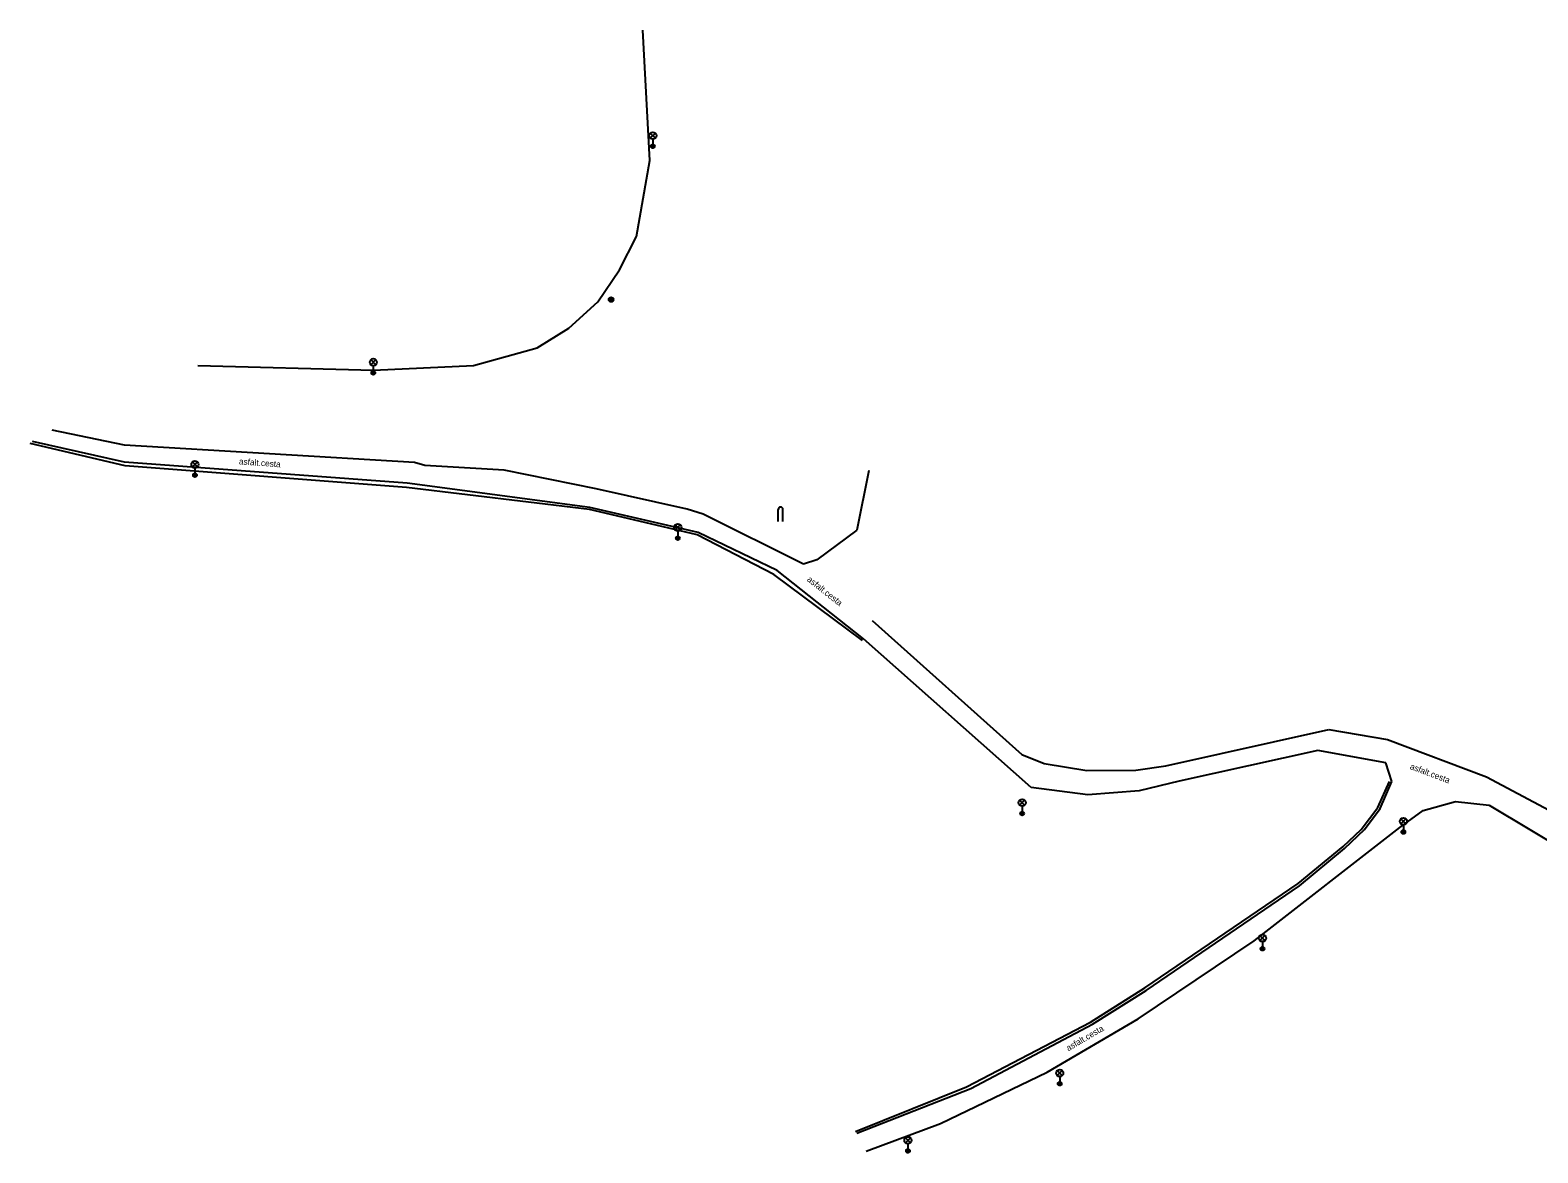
# Model space of a CAD drawing. Extents: x -639371 to -639058, y -1138650 to -1138362.
# Drawn here: x -639371.1 to -639212.8, y -1138642.6 to -1138524.7 of the extents above; entities that cross this region are included whole.
import ezdxf

# ---------------------------------------------------------------- set-up
doc = ezdxf.new("R2010")
doc.units = 0
for name, color, linetype in [('Vrstva 11', 7, 'Continuous'), ('Vrstva 25', 7, 'Continuous'), ('Vrstva 33', 7, 'Continuous'), ('Vrstva 38', 7, 'Continuous'), ('Vrstva 40', 7, 'Continuous'), ('Vrstva 9', 7, 'Continuous')]:
    doc.layers.add(name, color=color, linetype=linetype)

msp = doc.modelspace()

# ---------------------------------------------------------------- linework, layer by layer
at = {"layer": 'Vrstva 11'}
for p, q in [((-639361.16, -1138568.24), (-639368.75, -1138566.66)), ((-639361.16, -1138570.04), (-639370.81, -1138567.86)), ((-639330.69, -1138570.07), (-639361.16, -1138568.24)), ((-639331.46, -1138572.23), (-639361.16, -1138570.04)), ((-639329.62, -1138570.37), (-639330.69, -1138570.07)), ((-639321.27, -1138570.85), (-639329.62, -1138570.37)), ((-639311.61, -1138572.82), (-639321.27, -1138570.85)), ((-639283, -1138570.89), (-639284.26, -1138577.18)), ((-639312.29, -1138574.79), (-639331.46, -1138572.23)), ((-639302.07, -1138574.96), (-639311.61, -1138572.82)), ((-639300.92, -1138577.4), (-639312.29, -1138574.79)), ((-639300.38, -1138575.5), (-639302.07, -1138574.96)), ((-639289.86, -1138580.73), (-639300.38, -1138575.5)), ((-639292.61, -1138581.41), (-639300.92, -1138577.4)), ((-639284.26, -1138577.18), (-639288.44, -1138580.29)), ((-639283.55, -1138588.58), (-639292.61, -1138581.41)), ((-639288.44, -1138580.29), (-639289.86, -1138580.73)), ((-639282.64, -1138586.64), (-639266.93, -1138600.74)), ((-639265.95, -1138604.18), (-639283.55, -1138588.58)), ((-639251.8, -1138601.92), (-639234.71, -1138598.09)), ((-639234.71, -1138598.09), (-639228.53, -1138599.15)), ((-639235.85, -1138600.3), (-639250.41, -1138603.54)), ((-639228.72, -1138601.59), (-639235.85, -1138600.3)), ((-639228.53, -1138599.15), (-639218.13, -1138603.06)), ((-639266.93, -1138600.74), (-639264.57, -1138601.67)), ((-639264.57, -1138601.67), (-639260.09, -1138602.42)), ((-639254.95, -1138602.39), (-639251.8, -1138601.92)), ((-639228.08, -1138603.56), (-639228.72, -1138601.59)), ((-639260.09, -1138602.42), (-639254.95, -1138602.39)), ((-639250.41, -1138603.54), (-639254.61, -1138604.56)), ((-639229.32, -1138606.4), (-639228.08, -1138603.56)), ((-639218.13, -1138603.06), (-639209.92, -1138607.44)), ((-639259.99, -1138604.98), (-639265.95, -1138604.18)), ((-639254.61, -1138604.56), (-639259.99, -1138604.98)), ((-639230.97, -1138608.59), (-639229.32, -1138606.4)), ((-639227.26, -1138608.39), (-639224.79, -1138606.61)), ((-639224.79, -1138606.61), (-639221.39, -1138605.67)), ((-639221.39, -1138605.67), (-639217.88, -1138606.06)), ((-639217.88, -1138606.06), (-639207.21, -1138612.43)), ((-639242.53, -1138620.3), (-639227.26, -1138608.39)), ((-639233.07, -1138610.6), (-639230.97, -1138608.59)), ((-639237.77, -1138614.51), (-639233.07, -1138610.6)), ((-639253.88, -1138625.5), (-639237.77, -1138614.51)), ((-639254.71, -1138628.49), (-639242.53, -1138620.3)), ((-639259.52, -1138629.07), (-639253.88, -1138625.5)), ((-639272.3, -1138635.8), (-639259.52, -1138629.07)), ((-639264.28, -1138634.11), (-639254.71, -1138628.49)), ((-639275.46, -1138639.47), (-639264.28, -1138634.11)), ((-639284.25, -1138640.49), (-639272.3, -1138635.8)), ((-639283.29, -1138642.38), (-639275.46, -1138639.47))]:
    msp.add_line(p, q, dxfattribs=at)
at = {"layer": 'Vrstva 25'}
for radius in [0.25, 0.2, 0.15, 0.1, 0.05]:
    msp.add_circle((-639310.06, -1138552.95), radius, dxfattribs=at)
at = {"layer": 'Vrstva 33'}
for p, q in [((-639305.94, -1138535.99), (-639305.41, -1138535.46)), ((-639305.94, -1138535.46), (-639305.41, -1138535.99)), ((-639305.67, -1138536.1), (-639305.67, -1138536.85)), ((-639335.29, -1138559.79), (-639334.76, -1138559.26)), ((-639335.29, -1138559.26), (-639334.76, -1138559.79)), ((-639335.02, -1138559.9), (-639335.02, -1138560.65)), ((-639354.02, -1138570.53), (-639353.48, -1138570)), ((-639354.02, -1138570), (-639353.48, -1138570.53)), ((-639353.75, -1138570.64), (-639353.75, -1138571.39)), ((-639303.32, -1138577.15), (-639302.79, -1138576.62)), ((-639303.32, -1138576.62), (-639302.79, -1138577.15)), ((-639303.05, -1138577.26), (-639303.05, -1138578.01)), ((-639267.17, -1138606.06), (-639266.64, -1138605.53)), ((-639267.17, -1138605.53), (-639266.64, -1138606.06)), ((-639266.9, -1138606.17), (-639266.9, -1138606.92)), ((-639227.14, -1138608.01), (-639226.6, -1138607.48)), ((-639227.14, -1138607.48), (-639226.6, -1138608.01)), ((-639226.87, -1138608.12), (-639226.87, -1138608.87)), ((-639241.93, -1138620.27), (-639241.4, -1138619.74)), ((-639241.93, -1138619.74), (-639241.4, -1138620.27)), ((-639241.66, -1138620.38), (-639241.66, -1138621.13)), ((-639263.21, -1138634.45), (-639262.69, -1138633.92)), ((-639263.21, -1138633.92), (-639262.69, -1138634.45)), ((-639262.95, -1138634.56), (-639262.95, -1138635.31)), ((-639279.16, -1138641.51), (-639278.62, -1138640.98)), ((-639279.16, -1138640.98), (-639278.62, -1138641.51)), ((-639278.89, -1138641.62), (-639278.89, -1138642.37))]:
    msp.add_line(p, q, dxfattribs=at)
for centre, radius in [((-639305.67, -1138535.73), 0.375), ((-639305.67, -1138536.85), 0.2), ((-639305.67, -1138536.85), 0.145), ((-639305.67, -1138536.85), 0.0876), ((-639335.02, -1138559.53), 0.375), ((-639335.02, -1138560.65), 0.2), ((-639335.02, -1138560.65), 0.145), ((-639335.02, -1138560.65), 0.0876), ((-639353.75, -1138570.27), 0.375), ((-639353.75, -1138571.39), 0.2), ((-639353.75, -1138571.39), 0.145), ((-639353.75, -1138571.39), 0.0876), ((-639303.05, -1138576.89), 0.375), ((-639303.05, -1138578.01), 0.2), ((-639303.05, -1138578.01), 0.145), ((-639303.05, -1138578.01), 0.0876), ((-639266.9, -1138605.79), 0.375), ((-639266.9, -1138606.92), 0.2), ((-639266.9, -1138606.92), 0.145), ((-639266.9, -1138606.92), 0.0876), ((-639226.87, -1138607.75), 0.375), ((-639226.87, -1138608.87), 0.2), ((-639226.87, -1138608.87), 0.145), ((-639226.87, -1138608.87), 0.0876), ((-639241.66, -1138620.01), 0.375), ((-639241.66, -1138621.13), 0.2), ((-639241.66, -1138621.13), 0.145), ((-639241.66, -1138621.13), 0.0876), ((-639262.95, -1138634.19), 0.375), ((-639262.95, -1138635.31), 0.2), ((-639262.95, -1138635.31), 0.145), ((-639262.95, -1138635.31), 0.0876), ((-639278.89, -1138641.25), 0.375), ((-639278.89, -1138642.37), 0.2), ((-639278.89, -1138642.37), 0.145), ((-639278.89, -1138642.37), 0.0876)]:
    msp.add_circle(centre, radius, dxfattribs=at)
at = {"layer": 'Vrstva 38'}
for points in [[(-639292.51, -1138576.25), (-639292.51, -1138575)], [(-639292.01, -1138576.25), (-639292.01, -1138575)]]:
    msp.add_lwpolyline(points, dxfattribs=at)
msp.add_arc((-639292.26, -1138575), 0.25, 0, 180, dxfattribs=at)
at = {"layer": 'Vrstva 9'}
for p, q in [((-639305.98, -1138538.35), (-639306.73, -1138524.65)), ((-639307.38, -1138546.31), (-639305.98, -1138538.35)), ((-639309.16, -1138549.82), (-639307.38, -1138546.31)), ((-639311.46, -1138553.18), (-639309.16, -1138549.82)), ((-639314.5, -1138555.95), (-639311.46, -1138553.18)), ((-639317.82, -1138558.02), (-639314.5, -1138555.95)), ((-639324.49, -1138559.86), (-639317.82, -1138558.02)), ((-639353.46, -1138559.88), (-639334.99, -1138560.38)), ((-639334.99, -1138560.38), (-639324.49, -1138559.86)), ((-639361.07, -1138570.41), (-639371.05, -1138568.05)), ((-639331.52, -1138572.67), (-639361.07, -1138570.41)), ((-639312.32, -1138574.99), (-639331.52, -1138572.67)), ((-639301.02, -1138577.65), (-639312.32, -1138574.99)), ((-639292.96, -1138581.83), (-639301.02, -1138577.65)), ((-639283.67, -1138588.77), (-639292.96, -1138581.83)), ((-639229.54, -1138606.31), (-639228.34, -1138603.58)), ((-639231.29, -1138608.59), (-639229.54, -1138606.31)), ((-639233.21, -1138610.4), (-639231.29, -1138608.59)), ((-639237.93, -1138614.28), (-639233.21, -1138610.4)), ((-639254.02, -1138625.23), (-639237.93, -1138614.28)), ((-639259.71, -1138628.86), (-639254.02, -1138625.23)), ((-639272.75, -1138635.65), (-639259.71, -1138628.86)), ((-639284.38, -1138640.33), (-639272.75, -1138635.65))]:
    msp.add_line(p, q, dxfattribs=at)

# ---------------------------------------------------------------- texts
at = {"layer": 'Vrstva 40'}
for rotation, p in [(355.7828, (-639349.15, -1138570.25)), (321.6422, (-639289.54, -1138582.45)), (339.3957, (-639226.24, -1138602.23)), (30.4237, (-639262.05, -1138631.91))]:
    msp.add_text('asfalt.cesta', height=0.65, rotation=rotation, dxfattribs=at).set_placement(p)

doc.saveas('drawing.dxf')
